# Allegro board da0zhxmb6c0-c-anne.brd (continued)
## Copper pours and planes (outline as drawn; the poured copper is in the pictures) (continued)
GND on BOTTOM (solid shape): 115.57,111.54 116.64,111.54 116.76,111.42 116.76,111.06 116.61,110.91 115.57,110.91 115.27,110.61 115.27,110.05 115.1,109.88 110.06,109.88 109.91,110.03 109.91,111.4 113.67,111.4 113.67,111.34 113.68,111.29 113.69,111.24 113.72,111.19 113.75,111.14 113.79,111.1 113.83,111.07 113.87,111.04 113.93,111.02 113.98,111.01 114.03,111.01 114.09,111.01 114.14,111.02 114.19,111.04 114.24,111.07 114.28,111.1 114.32,111.14 114.35,111.19 114.37,111.24 114.39,111.29 114.39,111.34 114.39,111.4 114.39,111.45 114.37,111.5 114.35,111.55 114.32,111.6 114.28,111.64 114.24,111.67 114.19,111.7 114.14,111.72 114.09,111.73 114.03,111.73 113.98,111.73 113.93,111.72 113.87,111.7 113.83,111.67 113.79,111.64 113.75,111.6 113.72,111.55 113.69,111.5 113.68,111.45 113.67,111.4 109.91,111.4 109.91,111.52 110.25,111.85 115.26,111.85
GND on BOTTOM (solid shape): 55.58,84.32 55.58,83.33 55.57,83.33 55.57,82.05 55.58,82.05 55.58,81.85 55.35,81.63 52.48,81.63 51.31,82.79 47.33,82.79 47.14,82.61 46.56,82.61 46.42,82.75 46.42,83.13 46.84,83.56 46.84,83.56 54.38,83.56 54.38,83.5 54.38,83.45 54.4,83.4 54.42,83.35 54.45,83.3 54.49,83.26 54.53,83.23 54.58,83.2 54.63,83.18 54.68,83.17 54.74,83.17 54.79,83.17 54.85,83.18 54.9,83.2 54.94,83.23 54.98,83.26 55.02,83.3 55.05,83.35 55.08,83.4 55.09,83.45 55.1,83.5 55.1,83.56 55.09,83.61 55.08,83.66 55.05,83.71 55.02,83.76 54.98,83.8 54.94,83.83 54.9,83.86 54.85,83.88 54.79,83.89 54.74,83.89 54.68,83.89 54.63,83.88 54.58,83.86 54.53,83.83 54.49,83.8 54.45,83.76 54.42,83.71 54.4,83.66 54.38,83.61 54.38,83.56 46.84,83.56 46.84,85.72 47.12,85.99 53.9,85.99
GND on BOTTOM (solid shape): 111.51,61.56 111.51,61.05 111.61,60.95 111.63,60.93 111.64,60.77 111.7,60.65 111.72,60.58 111.68,60.51 111.79,59.87 112.22,60.35 112.23,60.45 112.32,60.49 113.86,60.49 114.42,59.93 116.87,59.93 117.02,59.78 117.02,57.72 116.85,57.56 116.85,57.51 116.74,57.39 113.69,57.39 113.67,57.42 113.16,57.42 113.13,57.39 110.26,57.39 109.86,57.8 109.86,61.69 110.24,62.07 111,62.07
GND on BOTTOM (solid shape): outline of 89 points within 113.21,99.15 121.41,107.53
GND on BOTTOM (solid shape): 22.13,72.88 22.13,64.9 21.57,64.34 18.32,64.34 17.17,63.19 15.78,63.19 14.61,64.35 11.74,64.35 11.46,64.63 11.46,66.1 10.71,67.07 9.58,66.61 7.57,66.61 2.66,66.61 2.66,68.75 2.36,69.46 1.65,69.76 1.41,69.76 1.41,70.74 2.66,70.74 7.52,70.74 8.21,71.24 8.01,72.06 8.01,72.92 8.33,73.24 21.77,73.24
GND on BOTTOM (solid shape): outline of 86 points within 127.38,56.07 136.91,60.67
GND on BOTTOM (solid shape): 83.25,65.42 83.29,65.41 83.37,65.37 83.46,65.35 83.48,65.35 83.56,65.27 83.55,65.24 83.63,64.94 83.94,64.88 83.97,64.89 83.99,64.87 84.92,64.87 85.27,64.52 85.22,64.47 85.19,64.47 84.72,64.47 84.61,64.58 84.13,64.58 84.07,64.64 83.59,64.64 83.34,64.39 83.3,64.42 83.1,64.47 82.91,64.38 82.84,64.35 82.76,64.38 82.71,64.42 82.65,64.46 82.6,64.51 82.59,64.58 82.6,64.67 82.59,64.76 82.6,64.83 82.65,64.88 82.8,65.01 82.84,65.2 82.84,65.22 82.88,65.28 82.91,65.28 83.08,65.31 83.22,65.41
GND on BOTTOM (solid shape): 59.55,65.42 59.58,65.41 59.72,65.31 59.89,65.28 59.92,65.28 59.96,65.23 59.96,65.2 60,65.01 60.15,64.88 60.2,64.83 60.21,64.76 60.2,64.67 60.21,64.58 60.2,64.51 60.15,64.46 60.09,64.42 60.04,64.38 59.96,64.35 59.89,64.38 59.7,64.47 59.5,64.42 59.46,64.4 59.18,64.68 58.77,64.68 58.67,64.58 58.2,64.58 58.08,64.46 57.91,64.46 57.86,64.51 57.31,64.51 57.21,64.58 57.24,64.69 57.44,64.89 58.85,64.89 58.86,64.89 59.17,64.94 59.25,65.24 59.24,65.27 59.32,65.35 59.34,65.35 59.43,65.37 59.51,65.41
GND on BOTTOM (solid shape): 136.6,106.06 137.95,106.06 138.1,105.91 138.13,105.91 138.7,105.34 142.66,105.34 142.85,105.15 147.54,105.15 147.74,104.94 147.74,104.45 146.89,103.6 144.71,103.6 143.14,102.02 143.14,99.26 142.43,98.55 140.38,98.55 139.84,98.01 136.4,98.01 135.89,97.5 135.89,96.99 135.38,96.48 135.28,96.48 134.44,95.65 134.11,95.65 134.06,95.7 134.05,95.72 134.04,95.74 134.04,97 134.49,97.45 134.49,100.55 134.75,100.8 135.74,100.8 135.86,100.92 135.98,100.94 136.04,100.85 136.02,100.81 136.01,100.8 136.28,100.19 136.52,100.81 136.51,100.83 136.51,100.85 136.51,102.28 136.29,102.5 136.29,102.67 136.28,102.74 136.24,102.8 136.18,102.85 136.12,102.87 136.1,102.87 136,102.98 135.72,102.98 135.63,103.07 135.63,104.85 134.72,105.76 134.72,106.16 134.87,106.31 136.35,106.31
GND on BOTTOM (solid shape): 73.76,60.74 73.81,60.73 73.85,60.73 73.92,60.71 73.95,60.64 73.99,60.51 74.08,60.4 74.11,60.33 74.08,60.25 74.01,60.17 73.97,60.09 73.95,60.06 73.91,60.05 73.67,60.01 73.54,59.8 73.5,59.73 73.41,59.71 73.21,59.69 73.07,59.53 73.06,59.5 72.71,59.5 72.61,59.6 72.6,59.61 72.59,59.65 72.61,59.68 72.71,59.82 72.73,59.99 72.73,60.02 72.79,60.06 72.81,60.06 73,60.1 73.13,60.25 73.18,60.3 73.25,60.31 73.58,60.38 73.73,60.69 73.73,60.71
GND on BOTTOM (solid shape): 77.41,78.58 77.44,78.56 77.47,78.53 77.47,78.51 77.56,78.35 77.74,78.29 77.76,78.28 77.78,78.27 77.98,78.07 77.98,77.62 77.98,77.61 77.97,77.59 77.9,77.41 77.97,77.24 77.98,77.22 77.98,77.21 77.98,76.8 77.85,76.67 77.69,76.67 77.62,76.7 77.59,76.77 77.56,76.9 77.49,77.01 77.48,77.04 77.49,77.08 77.59,77.24 77.58,77.43 77.37,77.8 76.96,77.71 76.94,77.69 76.92,77.69 76.68,77.69 76.59,77.78 76.59,77.88 76.82,78.11 76.82,78.27 76.83,78.29 76.85,78.31 76.93,78.37 76.98,78.46 76.98,78.47 77.06,78.55 77.08,78.56 77.25,78.54 77.38,78.57
GND on BOTTOM (solid shape): 13.22,96.52 13.22,93.68 13.72,92.29 13.14,90.93 13.14,90.47 11.53,88.86 11.53,87.98 12.42,87.09 12.42,86 11.99,85.56 8.21,85.56 8.01,85.76 8.01,85.94 8.21,86.76 7.52,87.26 2.79,87.26 1.41,87.26 1.41,88.29 1.91,88.66 2.11,89.25 2.11,91.34 2.79,91.34 11.7,91.34 12.67,92.09 12.21,93.22 12.21,96.51 12.45,96.76 12.99,96.76
GND on BOTTOM (solid shape): 82,60.89 82.07,60.88 82.11,60.81 82.34,60.54 82.69,60.6 82.7,60.61 82.94,60.63 82.95,60.63 83.17,60.64 83.32,60.79 83.36,60.82 83.4,60.81 83.41,60.8 83.43,60.76 83.41,60.72 83.3,60.52 83.34,60.29 83.34,60.19 83.25,60.14 83.22,60.14 83.21,60.14 83.04,60.19 82.88,60.14 82.87,60.14 82.66,60.14 82.65,60.14 82.5,60.18 82.35,60.14 82.34,60.14 82.25,60.14 82.14,60.04 82.14,59.78 82.07,59.71 81.92,59.71 81.82,59.8 81.82,60.22 81.82,60.24 81.8,60.35 81.75,60.45 81.73,60.53 81.77,60.6 81.87,60.71 81.92,60.85 81.93,60.88 81.97,60.89
GND on BOTTOM (solid shape): 87.15,82.18 87.15,82.13 87.21,81.99 87.35,81.93 87.65,81.93 87.71,81.94 87.77,81.96 87.78,81.97 87.82,81.97 87.89,81.91 87.89,81.09 87.86,81.06 87.86,80.61 87.38,80.14 87.31,80.13 87.23,80.12 87.08,80.06 87.02,79.92 87.02,79.8 87.02,79.73 87.01,79.71 86.69,79.39 85.29,79.39 85.15,79.54 85.05,79.54 85.01,79.57 84.15,79.57 83.97,79.75 83.97,80.18 84.18,80.38 84.21,80.39 84.39,80.45 84.49,80.61 84.49,80.62 84.69,80.82 84.89,80.82 84.91,80.81 85.13,80.6 85.13,80.58 85.45,80.22 85.83,80.5 85.84,80.52 85.85,80.53 85.85,80.89 85.42,81.32 85.4,81.33 85.18,81.4 84.96,81.32 84.5,81.32 84.37,81.19 84.09,81.19 83.52,81.76 83.52,81.99 83.7,82.17 83.7,82.46 83.61,82.56 83.61,82.8 84.01,83.2 86.13,83.2
GND on BOTTOM (solid shape): outline of 119 points within 94.31,97.53 103.56,107.2
GND on BOTTOM (solid shape): outline of 146 points within 133.12,78.73 145.75,90.85
GND on BOTTOM (solid shape): 6.73,8.85 7.01,7.29 6.46,5.8 5.75,5.09 5.26,4.8 4.71,4.61 4.32,4.52 4.32,1.52 6.32,1.52 6.39,1.95 6.44,2.25 6.5,2.55 6.6,2.72 6.59,2.93 6.81,3.64 7.08,4.33 7.39,4.54 7.36,4.91 7.77,5.62 8.25,6.3 9.34,6.3 9.44,6.24 9.42,6.13 8.02,3.95 7.35,1.45 7.33,1.45 7.3,0.97 7.15,0.64 6.81,0.51 3.8,0.51 3.45,0.65 3.31,1 3.31,5.54 4,5.54 5.78,6.62 5.65,8.7 5.71,8.77 5.76,8.85
GND on BOTTOM (solid shape): outline of 169 points within 58.9,88.27 67.76,91.86
GND on BOTTOM (solid shape): 77.43,64.62 77.52,64.63 77.58,64.57 77.72,64.36 77.96,64.29 77.98,64.29 78.01,64.25 78.01,64.23 78.2,63.89 78.57,64.03 78.66,64.08 78.75,64.03 78.84,63.92 78.97,63.87 79,63.87 79.02,63.83 79.01,63.8 79.05,63.47 79.33,63.3 79.4,63.26 79.42,63.19 79.48,63.01 79.64,62.89 79.7,62.84 79.71,62.77 79.71,62.73 79.7,62.68 79.69,62.65 79.66,62.63 79.53,62.58 79.44,62.47 79.41,62.45 79.37,62.45 79.22,62.49 79.06,62.45 79.02,62.48 79.02,62.5 78.97,62.63 78.87,62.72 78.82,62.81 78.87,62.9 78.91,63.4 78.43,63.25 78.38,63.2 78.31,63.19 78.19,63.19 78.07,63.17 78.03,63.19 78.03,63.22 77.92,63.41 77.72,63.48 77.64,63.5 77.61,63.57 77.57,63.71 77.47,63.82 77.44,63.9 77.47,63.97 77.59,64.27 77.43,64.54 77.4,64.58 77.43,64.62
GND on BOTTOM (solid shape): outline of 82 points within 76.47,59.37 78.62,63.18
GND on BOTTOM (solid shape): outline of 571 points within 2.11,97.59 152.08,115.49
GND on BOTTOM (solid shape): outline of 528 points within 111.01,32.96 131.71,40.73
GND on BOTTOM (solid shape): outline of 1092 points within 16.41,9.41 158.36,91.52
GND on BOTTOM (solid shape): outline of 11624 points within 57.57,57.72 85.2,83.91
GND on VCC (solid shape): outline of 314 points within 123.34,32.88 129.51,41.98
GND on VCC (solid shape): outline of 607 points within 66.93,93.56 79,99.91
GND on VCC (solid shape): outline of 1890 points within 98.43,71.97 117.98,92.29
GND on VCC (solid shape): outline of 1797 points within 2.87,2.03 26.42,36.41
GND on VCC (solid shape): outline of 2600 points within 3.6,50.76 33.4,95.11
GND on VCC (solid shape): outline of 4444 points within 114.68,20.43 159.61,112.47
GND on VCC (solid shape): outline of 28074 points within 33.91,32.86 112.4,73.24
GND on IN1 (solid shape): 10.8,19.85 10.8,17.14 10.57,16.91 6.63,16.91 6.35,17.19 6.35,19.8 6.53,19.98 10.67,19.98
GND on IN1 (solid shape): 27.43,26.99 27.43,24.98 27.31,24.86 25.32,24.86 25.12,25.06 25.12,26.99 25.32,27.19 27.23,27.19
GND on IN1 (solid shape): 41.99,66.14 41.99,64.3 41.89,64.2 39.57,64.2 39.45,64.33 39.45,66.41 39.65,66.61 41.51,66.61
GND on IN1 (solid shape): 99.92,23.84 99.92,22.24 99.67,21.99 98.25,21.99 98.05,22.19 98.05,23.97 98.1,24.02 99.75,24.02
GND on IN1 (solid shape): 30.08,64.83 30.08,62.18 29.79,61.89 27.1,61.89 26.9,62.09 26.9,64.23 27.16,64.49 27.16,65.2 27.26,65.29 29.61,65.29
GND on IN1 (solid shape): 33.05,58.12 33.05,57.56 32.47,56.97 32.46,56.96 32.46,55.06 32.13,54.73 29.49,54.73 28.91,55.31 28.91,58.18 29.11,58.38 32.79,58.38
GND on IN1 (solid shape): 12.47,52.4 12.29,51.56 11.78,50.88 3.67,50.88 3.67,49.64 3.34,49.31 3.34,49.29 2.92,49.29 2.66,49.56 2.66,51.89 8.38,51.89 9.58,51.89 9.78,51.65 10.05,51.48 10.45,51.39 10.85,51.48 11.29,51.85 11.46,52.4 11.46,53.38 11.64,53.56 12.47,53.56
GND on IN1 (solid shape): 6.73,8.85 6.73,6.25 4.71,4.61 4.32,4.52 4.32,1.52 6.32,1.52 6.39,1.95 6.43,2.23 6.49,2.5 6.63,2.72 6.61,2.98 6.81,3.65 7.07,4.3 7.42,4.53 7.37,4.94 8.67,6.82 10.38,8.33 10.94,8.33 11.13,8.14 11.13,7.61 8.55,4.95 7.35,1.45 7.33,1.45 7.3,0.97 7.15,0.64 6.81,0.51 3.8,0.51 3.45,0.65 3.31,1 3.31,5.54 4,5.54 5.66,6.41 5.87,8.27 5.77,8.49 5.65,8.7 5.71,8.77 5.76,8.85
GND on IN1 (solid shape): outline of 575 points within 2.11,96.75 152.02,115.49
GND on IN1 (solid shape): outline of 931 points within 28.27,14.11 157.74,91.52
GND on IN1 (solid shape): outline of 1253 points within 1.41,64.33 20.37,100.11
GND on IN2 (solid shape): 27.43,27.02 27.43,24.96 27.33,24.86 25.27,24.86 25.17,24.96 25.17,27.02 25.3,27.14 27.31,27.14
GND on IN2 (solid shape): 41.99,66.03 41.99,64.25 41.94,64.2 39.63,64.2 39.37,64.46 39.37,66.44 39.6,66.66 41.36,66.66
GND on IN2 (solid shape): 100.05,23.74 100.05,22.25 99.77,21.96 98.2,21.96 98.02,22.14 98.02,23.82 98.2,23.99 99.8,23.99
GND on IN2 (solid shape): 10.8,19.95 10.8,15.93 10.58,15.71 8.16,15.71 8.06,15.61 6.53,15.61 6.4,15.74 6.4,19.83 6.58,20.01 10.75,20.01
GND on IN2 (solid shape): 29.93,58.28 32.62,58.28 32.88,58.01 33.19,58.01 33.3,57.9 33.3,57.42 32.64,56.76 32.64,55.26 32.13,54.75 29.34,54.75 29.28,54.81 29.28,54.99 28.78,55.49 28.78,58.05 29.11,58.38 29.82,58.38
GND on IN2 (solid shape): 30.35,65.01 30.35,62.34 30.34,62.31 30.3,62.29 26.93,62.29 26.89,62.31 26.87,62.34 26.87,64.96 27.2,65.29 30.07,65.29
GND on IN2 (solid shape): 12.47,52.4 12.29,51.56 11.77,50.87 9.12,50.87 9.11,50.88 3.67,50.88 3.67,49.66 3.29,49.28 2.88,49.28 2.66,49.5 2.66,51.89 8.48,51.89 9.58,51.89 10.71,51.43 11.46,52.4 11.46,53.48 11.53,53.56 12.47,53.56
GND on IN2 (solid shape): 12.38,72.1 13.81,72.1 14.64,72.93 18.19,72.93 20.71,70.4 20.71,67.47 17.57,64.33 11.81,64.33 11.46,64.68 11.46,66.1 10.71,67.07 9.58,66.61 8.79,66.61 2.66,66.61 2.66,68.75 2.36,69.46 1.65,69.76 1.41,69.76 1.41,70.74 2.66,70.74 7.52,70.74 8.21,71.24 8.01,72.06 8.01,72.92 8.33,73.25 11.23,73.25
GND on IN2 (solid shape): 12.74,100.09 13.7,98.67 13.22,97.02 13.22,93.68 13.68,91.91 12.52,90.5 11.92,89.9 11.92,86.02 11.47,85.56 8.21,85.56 8.01,85.77 8.01,85.94 8.21,86.76 7.52,87.26 2.79,87.26 1.41,87.26 1.41,88.29 1.91,88.66 2.11,89.25 2.11,91.34 2.79,91.34 11.7,91.34 12.67,92.09 12.21,93.22 12.21,97.48 12.71,98.37 12.18,99.24 12.18,99.85 12.41,100.09
GND on IN2 (solid shape): 6.73,8.85 6.73,6.25 4.71,4.61 4.32,4.52 4.32,1.52 6.32,1.52 6.39,1.95 6.43,2.23 6.49,2.5 6.63,2.72 6.61,2.98 6.81,3.65 7.07,4.3 7.42,4.53 7.37,4.94 8.67,6.82 10.38,8.33 10.94,8.33 11.13,8.14 11.13,7.61 8.55,4.95 7.35,1.45 7.33,1.45 7.3,0.97 7.15,0.64 6.81,0.51 3.8,0.51 3.45,0.65 3.31,1 3.31,5.54 4,5.54 5.63,6.38 5.9,8.19 5.79,8.45 5.65,8.7 5.71,8.77 5.76,8.85
GND on IN2 (solid shape): outline of 514 points within 2.11,97.13 152.67,115.49
GND on IN2 (solid shape): outline of 620 points within 149.48,48.95 159.25,102.75
GND on IN2 (solid shape): outline of 628 points within 16.41,9.41 157.09,42.35
GND on GND (solid shape): outline of 90983 points within 1.41,0.51 162.79,115.49
24707_LX on TOP (solid shape): 91.92,23.54 91.92,22.8 92.06,22.66 92.15,22.66 92.15,22.65 93.18,22.65 93.18,22.66 94.03,22.66 94.34,22.34 94.34,22.19 94.58,21.96 95.87,21.96 95.93,21.96 96.62,22.65 96.88,22.65 96.93,22.6 97.62,22.6 97.7,22.52 97.7,22.43 97.65,22.38 96.99,22.38 96.95,22.34 96.92,22.34 96.92,22.31 96.83,22.22 96.82,22.22 96.82,22.2 96.79,22.18 96.79,21.76 96.33,21.3 92.09,21.3 91.57,21.82 91.57,21.82 90.27,23.12 90.27,23.95 90.43,24.11 91.35,24.11
24707_LX on BOTTOM (solid shape): 93.42,26.72 93.42,22.7 93.37,22.64 93.36,22.64 93.27,22.55 93.27,21.89 93.25,21.87 90.86,21.87 90.47,21.48 88.29,21.48 88.19,21.58 88.19,25.16 88.34,25.31 89.45,25.31 91.05,26.92 93.22,26.92
24737_BST on TOP (solid shape): 96.9,23.61 97.69,23.61 97.71,23.59 97.71,23.38 97.69,23.36 96.93,23.36 96.88,23.31 96.47,23.31 96.28,23.11 96.03,23.11 95.71,22.8 95.02,22.8 94.95,22.88 94.95,23.59 95,23.64 96.88,23.64
24737_DH on TOP (solid shape): 97.76,23.1 97.76,22.85 97.75,22.84 96.92,22.84 96.66,22.84 95.88,22.06 94.63,22.06 94.45,22.24 94.45,22.53 94.61,22.69 94.71,22.69 94.73,22.67 95.75,22.67 96.08,23 96.32,23 96.43,23.11 97.74,23.11
24737_DH on BOTTOM (solid shape): 94.96,22.63 94.96,22.56 95.05,22.47 95.08,22.44 95.08,22.35 94.66,21.93 93.97,21.93 93.91,21.87 93.48,21.87 93.48,22.57 93.62,22.72 94.87,22.72
24737_DL on TOP (solid shape): 97.94,25.04 98.04,25.04 98.11,25.01 98.15,24.94 98.15,24.32 98,24.32 97.94,24.26 96.96,24.26 96.92,24.22 96.82,24.22 96.82,24.22 95.08,24.22 94.77,24.53 94.77,24.83 94.92,24.98 95.35,24.98 95.65,24.68 95.66,24.68 95.79,24.55 96.34,24.55 96.85,25.06 97.83,25.06
24737_DL on BOTTOM (solid shape): 95.4,24.74 95.4,24.5 94.95,24.04 93.9,24.04 93.8,24.15 93.8,24.5 93.83,24.52 94.59,24.52 94.69,24.62 94.69,24.7 94.89,24.91 95.23,24.91
24737_REGN on TOP (solid shape): 93.41,27.51 93.41,25.78 93.69,25.5 94.2,25.5 94.57,25.13 94.57,24.43 94.88,24.12 97.71,24.12 97.75,24.08 97.75,23.86 97.74,23.85 96.92,23.85 96.84,23.76 94.73,23.76 94.59,23.9 93.97,23.9 92.44,25.44 92.44,27.58 92.69,27.83 93.09,27.83
51216DRVH on BOTTOM (solid shape): 21.16,44.34 21.16,43.68 21.74,43.09 21.74,42.21 21.62,42.08 21.06,42.08 20.63,42.51 20.63,44.26 20.75,44.39 21.11,44.39
51216DRVH on IN1 (solid shape): 22.02,43.78 22.02,42.15 21.95,42.08 21.26,42.08 21.23,42.11 21.23,43.8 21.34,43.91 21.9,43.91
51216DRVL on BOTTOM (solid shape): 28.58,47.18 28.58,46.93 28.33,46.69 27.73,46.69 27.56,46.52 27.13,46.52 27.08,46.57 27.08,47.31 27.13,47.36 27.56,47.36 27.64,47.29 27.89,47.29 27.99,47.39 28.37,47.39
51216SW on TOP (solid shape): 28.36,45.37 28.36,44.33 28.25,44.21 26.57,44.21 26.48,44.3 26.48,45.32 26.8,45.63 28.09,45.63
51216SW on BOTTOM (solid shape): 28.61,45.8 28.61,43.49 28.6,43.48 28.6,41.65 26.81,39.85 22.45,39.85 22.02,40.28 22.02,43.04 21.36,43.7 21.36,44.36 21.62,44.62 23.42,44.62 24.03,45.23 24.03,45.96 24.33,46.27 28.14,46.27
+CLKDDR_1P35_PWR on IN1 (solid shape): outline of 487 points within 71.51,50.87 73.27,66.83
+LCDVCC on BOTTOM (solid shape): 64.36,96.56 64.36,95.09 64.49,94.96 66.12,94.96 66.19,94.88 66.19,94.2 66.42,93.97 66.75,93.97 66.9,93.82 66.9,93.79 67.54,93.16 67.54,92.8 67.26,92.52 65.76,92.52 65.57,92.71 65.57,94.05 65.2,94.05 65.12,94.13 65.07,94.13 65.03,94.17 63.88,94.17 63.58,94.48 63.55,94.48 63.55,94.48 63.29,94.48 63.16,94.62 63.16,95.1 64.12,95.1 64.12,96.4 63.88,96.4 63.88,95.1 63.62,95.1 63.62,96.4 63.38,96.4 63.38,95.1 63.16,95.1 63.16,96.45 63.35,96.64 64.29,96.64
+PLLDDR_1P35_PWR on IN1 (solid shape): outline of 752 points within 68.24,49.47 71.44,66.79
+TPVDD_1 on TOP (solid shape): 47.08,26.12 47.08,25.42 47.43,25.06 48.09,25.06 48.1,25.05 48.57,25.05 48.9,24.73 48.9,21.53 47.7,20.34 45.37,20.34 45.29,20.41 45.29,20.67 44.83,21.12 44.83,22.19 45.34,22.7 45.98,22.7 46.36,23.08 46.36,24.48 46.23,24.6 46.23,26.25 46.35,26.38 46.82,26.38
+TPVDD_1 on BOTTOM (solid shape): 47.45,24.48 51.69,24.48 52.22,23.94 52.22,22.09 51.39,21.25 49.89,21.25 49.84,21.3 49.84,22.82 49.68,22.98 46.48,22.98 46.23,23.23 46.23,24.73 46.51,25.01 46.91,25.01
+TPVDD_1 on IN2 (solid shape): 47.3,25.01 47.3,23.48 46.86,23.04 46.42,23.04 46,23.46 46,25.26 46.1,25.36 46.94,25.36
+VGG on TOP (solid shape): outline of 763 points within 73,61.37 119.46,74.51
+VGG on BOTTOM (solid shape): 120.52,65.62 120.52,62.99 120.51,62.95 120.47,62.94 119.58,62.94 119.55,62.96 117.86,62.96 117.86,62.44 119.55,62.44 119.58,62.47 120.35,62.47 120.52,62.29 120.52,61.41 119.23,60.12 118.45,60.12 118.36,60.04 114.46,60.04 113.9,60.6 113.76,60.6 113.72,60.6 113.67,60.6 112.42,60.6 112.34,60.64 112.33,60.74 112.2,61.17 111.74,61.14 111.71,61.13 111.67,61.14 111.63,61.18 111.63,61.81 111.25,62.19 110.24,62.19 110.03,62.4 110.03,63.7 110.04,63.72 110.05,63.73 110.21,63.9 110.21,66.69 110.41,66.89 119.25,66.89
+VGG on BOTTOM (solid shape): outline of 96 points within 72.73,67.57 77.46,71.08
+VGG on VCC (solid shape): outline of 4973 points within 72.42,59.65 119.76,80.36
ADOGND on TOP (solid shape): 10.04,26.15 10.04,25.51 10.06,25.49 10.06,25.3 10.04,25.28 10.04,24.69 9.96,24.6 8.99,24.6 8.81,24.78 8.81,26.13 8.89,26.2 9.98,26.2
ADOGND on TOP (solid shape): 2.29,34.26 2.29,32.73 3.91,31.1 3.91,27.78 4.44,27.25 4.44,25.77 3.66,24.98 3.66,23.74 3.25,23.33 3.25,18.22 3.24,18.2 3.23,18.18 3.1,17.92 3.21,17.65 3.22,17.63 3.23,17.61 3.23,17.01 2.69,16.47 2.69,13.86 2.97,13.58 3.2,13.58 3.33,13.45 3.33,11.88 3.4,11.8 4.98,11.8 5.41,12.23 5.41,12.37 5.51,12.47 5.91,12.47 5.97,12.41 5.97,11.01 5.93,10.98 5.69,10.98 5.47,11.19 2.87,11.19 2.39,10.71 2.39,10.04 2.38,9.85 2.38,9.67 2.36,9.59 2.28,9.56 0.56,9.56 0.52,9.57 0.51,9.61 0.51,34.59 0.52,34.63 0.56,34.64 1.91,34.64
ADOGND on TOP (solid shape): 13.39,48.44 13.8,48.11 14.12,47.69 14.35,46.99 14.32,46.24 14.15,45.78 13.87,45.37 13.87,41.48 14.37,40.23 13.97,38.94 13.95,38.92 13.93,38.91 13.3,38.91 13.03,39.18 13.03,39.38 13.04,39.41 13.05,39.42 13.35,40.25 12.88,41.01 12.86,41.02 12.86,41.05 12.86,45.8 12.86,45.83 12.88,45.84 13.36,46.68 12.92,47.53 12.9,47.55 12.9,47.57 12.9,48.2 13.14,48.44 13.35,48.44
ADOGND on BOTTOM (solid shape): 1.52,34.49 1.52,10.57 2.07,10.57 2.29,10.35 2.29,9.66 2.19,9.56 0.51,9.56 0.51,34.64 1.37,34.64
ADOGND on BOTTOM (solid shape): 13.39,48.44 13.8,48.11 14.12,47.69 14.35,46.99 14.32,46.24 14.15,45.78 13.87,45.37 13.87,41.48 14.36,40.34 14.09,39.12 14.07,39.1 14.05,39.09 13.12,39.09 13.03,39.18 13.03,39.38 13.04,39.41 13.05,39.42 13.35,40.25 12.88,41.01 12.86,41.02 12.86,41.05 12.86,45.8 12.86,45.83 12.88,45.84 13.36,46.68 12.92,47.53 12.9,47.55 12.9,47.57 12.9,48.2 13.14,48.44 13.35,48.44
ADOGND on VCC (solid shape): outline of 1376 points within 2.03,9.36 18.29,50.18
ADOGND on IN1 (solid shape): 1.52,34.39 1.52,10.57 2.04,10.57 2.29,10.33 2.29,9.69 2.16,9.56 0.51,9.56 0.51,34.64 1.27,34.64
ADOGND on IN1 (solid shape): 13.39,48.44 14.35,47.02 13.87,45.37 13.87,41.48 14.37,40.21 13.95,38.91 13.3,38.91 13.03,39.18 13.03,39.41 13.35,40.26 12.86,41.02 12.86,45.83 13.36,46.68 12.9,47.55 12.9,48.2 13.14,48.44 13.35,48.44
ADOGND on IN2 (solid shape): 1.52,34.44 1.52,10.57 2.04,10.57 2.29,10.33 2.29,9.69 2.16,9.56 0.51,9.56 0.51,34.64 1.32,34.64
ADOGND on IN2 (solid shape): 14.37,48.2 14.37,45.65 13.87,45.15 13.87,41.48 14.37,40.19 13.92,38.88 13.18,38.88 12.96,39.1 12.96,39.35 13.36,40.21 12.86,41.02 12.86,45.83 13.35,46.57 13.06,47.41 13.06,48.38 13.29,48.61 13.97,48.61
ADOGND on GND (solid shape): outline of 1723 points within 0.51,9.36 18.29,50.18
BAT-V on TOP (solid shape): 82.93,26.19 82.93,18.25 82.83,18.15 77.7,18.15 77.42,18.43 77.42,21.86 77.24,22.04 77.23,22.08 77.24,22.1 77.31,22.24 77.32,22.41 77.06,22.85 76.57,22.7 76.48,22.65 76.4,22.69 76.09,22.87 75.75,22.73 75.68,22.7 75.6,22.73 75.12,22.83 74.89,22.39 74.89,22.28 74.92,22.16 74.91,22.07 74.83,22.02 67.91,22.02 66.17,20.28 62.61,20.28 61.72,21.17 61.72,26.51 62.69,27.47 81.65,27.47
BAT-V on BOTTOM (solid shape): 80.29,29.23 80.29,25.97 80.21,25.9 78.92,25.9 77.88,26.94 75.77,26.94 75.34,27.37 75.34,28.46 75.79,28.92 78.77,28.92 79.17,29.33 80.19,29.33
BAT-V on BOTTOM (solid shape): 66.68,28.72 66.68,23.31 66.66,23.29 66.66,21.11 65.91,20.36 62.26,20.36 61.06,21.55 61.06,23.76 59.46,25.36 59.46,28.62 59.77,28.92 62.54,28.92 62.79,28.67 65.43,28.67 65.81,29.05 66.35,29.05
BAT-V on IN2 (solid shape): outline of 589 points within 60.55,18.54 80.39,27.43
BMPD_1P05_PWR on TOP (solid shape): outline of 461 points within 70.11,74.05 75.01,85.09
BMPD_1P05_PWR on IN2 (solid shape): 73.02,77.27 73.04,77.27 73.06,77.25 73.13,77.19 73.22,77.15 73.23,77.14 73.66,76.71 73.66,76.55 73.62,76.47 73.52,76.46 73.04,76.12 73.52,75.79 73.61,75.78 73.66,75.69 73.66,75.18 73.58,75.1 73.55,75.1 72.99,74.55 72.9,74.52 72.83,74.57 72.35,74.74 72.19,74.26 72.18,74.16 72.1,74.11 71.6,74.11 71.5,74.22 71.5,75.96 71.56,76.05 71.67,76.03 72.01,75.69 72.65,75.69 72.65,76.33 72.08,76.89 72.07,76.93 72.08,76.96 72.39,77.27
CCD_PWR on TOP (solid shape): 66.32,101.64 66.32,97.07 66.23,96.97 65.4,96.97 65.15,97.22 65.15,99.27 65.23,99.35 65.33,99.65 65.17,99.91 65.16,99.93 65.15,99.95 65.15,101.59 65.33,101.77 66.19,101.77
CCD_PWR on BOTTOM (solid shape): 66.19,97.63 66.19,97.07 66.08,96.95 65.55,96.95 65.36,96.76 65.36,95.09 65.34,95.07 65.17,95.07 65.14,95.08 65.12,95.12 65.12,97.53 65.38,97.78 66.04,97.78
CF3_3P3_PWR on TOP (solid shape): 86.29,84.32 86.4,84.3 86.46,84.24 86.46,81.99 86.67,81.79 87.22,81.79 87.64,81.37 87.64,81.02 87.47,80.85 86.02,80.85 85.52,80.35 85.4,80.35 85.24,80.51 85.24,82.21 85.44,82.41 85.44,84.27 85.52,84.34 86.21,84.34
CORE_1P05_PWR on TOP (solid shape): outline of 751 points within 61.09,71.79 69.79,88.15
CORE_1P05_PWR on BOTTOM (solid shape): 64.91,88.15 65.1,88.1 65.3,88.15 66.22,88.15 66.35,88.02 66.35,87.1 66.33,87.08 66.31,87.07 66.08,86.91 65.96,86.66 65.94,86.63 65.91,86.62 65.79,86.62 65.69,86.52 65.66,86.5 65.63,86.51 65.5,86.56 65.36,86.58 65.29,86.58 65.26,86.59 65.24,86.6 64.73,86.88 64.25,86.55 64.17,86.49 64.08,86.52 63.09,87.5 63.09,87.93 63.32,88.15
CORE_1P05_PWR on BOTTOM (solid shape): 68.18,74.63 68.23,74.58 68.87,73.94 68.88,73.93 68.92,73.86 68.99,73.8 69.01,73.78 69.01,73.76 69.01,73.65 69.32,73.35 69.34,73.35 69.35,73.34 69.6,73.3 69.82,73.45 69.83,73.47 69.86,73.47 69.95,73.47 70.05,73.37 70.05,73.02 69.47,72.43 69.45,72.42 69.2,72.23 69.21,71.9 69.22,71.89 69.22,71.87 69.32,71.77 69.32,71.59 69.22,71.49 68.96,71.49 68.2,72.25 66.78,72.25 66.65,72.38 66.65,72.53 67.69,73.57 67.69,73.73 67.87,73.9 67.88,74.03 67.87,74.16 67.72,74.31 67.72,74.54 67.9,74.72 68.1,74.72
CORE_V1P15_PWR on TOP (solid shape): 96.82,66.92 101.83,66.92 101.86,66.89 101.86,66.23 101.71,66.09 100.84,66.09 100.81,66.06 100.54,66.06 100.51,66.09 99.48,66.09 99.45,66.06 97.76,66.06 97.75,66.06 97.61,66.09 97.47,66.06 97.46,66.06 96.83,66.06 96.4,66.48 96.4,66.49 96.34,66.6 96.24,66.65 96.23,66.65 95.64,67.24 95.64,67.77 95.78,67.91 95.83,67.91
CORE_V1P15_PWR on TOP (solid shape): outline of 138 points within 61.24,66 70.54,69.08
CORE_V1P15_PWR on IN1 (solid shape): outline of 268 points within 69.26,67.26 96.66,71.39
DDI_1P15_PWR on TOP (solid shape): 75.06,68.44 75.06,67.17 74.93,67.05 74.55,67.05 74.42,67.17 74.42,67.53 74.04,67.91 73.69,67.91 73.46,68.14 73.46,68.44 73.56,68.54 74.96,68.54
DDI_1P15_PWR on IN1 (solid shape): outline of 677 points within 67.69,66.58 84.25,69.43
DDR_1P05_PWR on TOP (solid shape): outline of 499 points within 73.1,64.23 86.36,66.89
DDR_1P05_PWR on BOTTOM (solid shape): 74.63,67.05 74.63,66.87 73.74,65.98 73.53,65.98 73.05,66.46 73.05,66.72 73.51,67.17 74.5,67.17
DDR_1P05_PWR on IN2 (solid shape): 73.61,66.69 73.61,66.11 73.22,65.71 70.3,65.71 70.05,65.95 69.66,65.95 69.46,66.02 69.26,65.95 68.67,65.95 68.57,66 68.46,66.02 68.44,66.02 68.28,66.18 68.28,66.4 68.32,66.49 68.34,66.58 68.34,66.6 68.39,66.65 68.59,66.85 69.01,66.85 69.24,66.61 70.44,66.61 70.74,66.31 70.79,66.31 70.79,66.3 71.06,66.22 71.3,66.36 71.31,66.38 71.39,66.41 71.47,66.37 71.78,66.23 72.06,66.41 72.15,66.46 72.24,66.41 72.65,66.25 72.9,66.62 72.9,66.77 73,66.87 73.43,66.87
EC_114 on BOTTOM (solid shape): 135.33,39.62 135.33,37.51 135.1,37.28 135.1,37.28 135.03,37.2 134.28,37.2 133.73,37.75 133.73,37.76 133.45,38.04 133.45,38.57 133.79,38.9 133.79,39.41 134.09,39.72 135.24,39.72
FUSE1_1P05_PWR on TOP (solid shape): outline of 348 points within 79,78.39 81.56,86.96
FUSE_1P05_PWR on TOP (solid shape): outline of 101 points within 74.63,75.02 76.43,86.82
FUSE_1P8_PWR on TOP (solid shape): outline of 140 points within 77.1,75.18 89.44,79.78
GPIOCF1_1P8_PWR on TOP (solid shape): outline of 106 points within 75.26,63.95 88.26,68.56
GPIOCF1_1P8_PWR on IN2 (solid shape): outline of 271 points within 68.42,67.1 77.06,70.88
GPIOCF2_1P8_PWR on TOP (solid shape): outline of 240 points within 76.05,73.19 89.45,78.32
HDMI_5V on TOP (solid shape): outline of 94 points within 9.64,82.41 16.77,86.27
ICLK_1P05_PWR on TOP (solid shape): outline of 185 points within 75.26,73.29 79.76,86.96
ICLK_VSFR_1P24_PWR on IN1 (solid shape): outline of 369 points within 68.66,73.24 71.49,78.7
L_SPK+ on TOP (solid shape): 32.56,27.7 32.56,26.43 32.49,26.36 31.78,26.36 31.07,27.07 31.07,27.73 31.24,27.9 32.36,27.9
L_SPK+ on TOP (solid shape): 8.49,15.18 8.49,13.43 8.34,13.29 8.34,12.41 8.2,12.26 7.97,12.26 7.83,12.4 7.83,13.38 8.29,13.83 8.29,15.18 8.29,15.19 8.48,15.19
L_SPK+ on IN2 (solid shape): 32.39,27.75 32.39,27.35 32.06,27.02 31.22,27.02 30.68,26.48 30.07,27.09 30.94,27.96 32.18,27.96
L_SPK+ on IN2 (solid shape): 12.36,15.85 11.21,14.71 8.99,14.71 8.3,14.02 8.3,11.67 8.25,11.62 7.96,11.62 7.84,11.73 7.84,13.35 7.84,13.35 7.84,13.79 7.93,13.88 7.93,15.12 8.27,15.45 10.72,15.45 11.41,16.14 12.07,16.14
L_SPK+_1 on TOP (solid shape): 35.22,27.45 35.22,26.37 35.21,26.36 33.02,26.36 32.84,26.53 32.84,27.55 33.17,27.88 34.79,27.88
L_SPK+_1 on BOTTOM (solid shape): 35.1,27.75 35.1,27.3 34.8,26.99 33.71,26.99 33.61,26.89 33.6,26.89 32.58,25.86 32.58,25.86 32.37,25.65 32.37,23.27 31.58,23.27 31.58,26.11 33.38,27.9 34.95,27.9
L_SPK- on TOP (solid shape): 31.62,26 32.08,26 32.56,25.52 32.56,24.55 32.46,24.45 31.34,24.45 30.71,25.09 30.71,26.23 30.84,26.36 31.27,26.36
L_SPK- on TOP (solid shape): 8.88,15.18 8.88,14.05 8.97,13.97 8.97,12.37 8.87,12.27 8.61,12.27 8.5,12.38 8.5,13.29 8.6,13.39 8.6,13.96 8.69,14.05 8.69,15.18 8.69,15.19 8.88,15.19
L_SPK- on IN2 (solid shape): 31.88,26.1 31.88,24.22 31.31,23.65 30.91,24.04 30.91,26.23 31.12,26.43 31.55,26.43
L_SPK- on IN2 (solid shape): 13.26,15.13 13.26,14.93 11.97,13.64 9.17,13.64 8.94,13.41 8.93,13.29 8.93,11.63 8.86,11.56 8.67,11.56 8.56,11.68 8.56,13.89 9.09,14.42 10.51,14.42 10.51,14.41 11.48,14.41 12.37,15.31 13.08,15.31
L_SPK-_1 on TOP (solid shape): 35.15,25.75 35.15,24.58 35.03,24.45 33.05,24.45 32.84,24.65 32.84,25.9 33.05,26.1 34.8,26.1
L_SPK-_1 on BOTTOM (solid shape): 34.85,26.43 34.85,25.7 34.7,25.54 33.72,25.54 33.62,25.44 33.62,23.27 32.83,23.27 32.83,25.76 33.71,26.63 34.65,26.63
LED_PWR on BOTTOM (solid shape): 64.87,97.63 64.87,95.16 64.86,95.13 64.82,95.11 64.67,95.11 64.62,95.16 64.62,96.4 64.62,96.4 64.62,96.69 64.06,97.25 64.06,97.78 64.21,97.93 64.57,97.93
LGATE_VCORE on BOTTOM (solid shape): 39.35,78.43 39.35,76.81 39.27,76.73 38.52,76.73 38.41,76.85 38.41,78.83 38.52,78.95 38.82,78.95
LGATE_VCORE on BOTTOM (solid shape): 40.36,69.43 40.47,69.36 40.6,69.33 40.62,69.33 40.77,69.18 40.77,68.47 40.59,68.29 40.59,67.22 40.58,67.19 40.54,67.17 40.44,67.17 40.41,67.19 40.39,67.22 40.39,68.12 40.39,68.12 40.39,68.16 40.3,68.25 40.3,68.27 39.91,68.66 39.91,69.27 40.07,69.43
LGATE_VGG on BOTTOM (solid shape): 126.82,60.34 126.82,59.35 126.32,58.84 126.04,58.84 125.1,59.78 125.1,60.16 125.35,60.42 126.74,60.42
LX_1P8 on BOTTOM (solid shape): 110.67,107.2 110.67,104.54 110.76,104.44 110.76,104.39 111.92,103.23 111.97,103.23 112.17,103.04 112.17,102.89 112.15,102.86 112.12,102.84 111.17,102.84 111.17,102.64 112.12,102.64 112.15,102.63 112.17,102.59 112.17,102.45 112.16,102.44 111.17,102.44 111.17,102.43 110.76,102.43 110.5,102.7 108.98,102.7 107.37,104.31 107.37,107.08 107.89,107.6 110.27,107.6
NB670SW on BOTTOM (solid shape): 134.9,95.32 134.9,92.32 135.21,92.01 135.21,89.32 134.93,89.04 134.93,88.86 133.61,87.54 131.34,87.54 130.28,88.61 130.28,93.36 130.38,93.46 130.79,93.46 131.24,93.01 133.17,93.01 133.43,93.26 133.43,95.29 133.63,95.49 134.72,95.49
NB671BST_S on BOTTOM (solid shape): 132.26,110.71 132.26,109.87 132.16,109.77 131.53,109.77 131.37,109.61 131.34,109.61 131.34,109.58 131.1,109.34 130.5,109.34 130.34,109.5 130.34,110.31 130.91,110.89 132.08,110.89
NB671SW on BOTTOM (solid shape): 130.28,109.21 130.76,109.21 130.84,109.13 130.84,108.6 132.08,107.36 132.69,107.36 133.05,107 134.32,107 134.51,106.81 134.51,105.59 134.37,105.45 133.22,105.45 133.22,105.45 133.15,105.45 132.54,104.83 132.54,103.95 131.88,103.29 129.03,103.29 128.8,103.52 128.8,103.98 128.81,103.99 128.82,104.01 129.11,104.3 129.11,105.06 128.8,105.36 128.8,109.16 129.18,109.53 129.95,109.53
PHASE_CORE on BOTTOM (solid shape): 43.15,77 43.18,76.99 43.2,76.95 43.2,76.49 43.17,76.46 43.17,74.77 43.7,74.77 43.7,76.46 43.67,76.49 43.67,76.95 43.69,76.99 43.72,77 45.95,77 46.15,76.8 46.15,74.64 45.09,73.57 35.08,73.57 34.88,73.78 34.88,75.58 35.03,75.73 40.62,75.73 41.89,77
PHASE_CORE on BOTTOM (solid shape): 42.93,69.76 42.93,68.89 42.92,68.86 42.9,68.84 42.8,68.78 42.73,68.69 42.71,68.67 42.69,68.67 42.39,68.67 42.37,68.65 42.27,68.65 41.78,68.16 41.78,67.22 41.77,67.19 41.73,67.17 41.64,67.17 41.61,67.19 41.59,67.22 41.59,68.12 41.58,68.12 41.58,68.24 41.5,68.32 41.5,69 41.89,69.38 41.89,69.97 42.09,70.17 42.52,70.17
PHASE_VGG on TOP (solid shape): 127.99,62.47 127.99,61.36 127.74,61.1 126.16,61.1 125.25,62.02 125.25,63.03 125.45,63.24 127.23,63.24
PHASE_VGG on BOTTOM (solid shape): 125.73,64.35 125.73,63.72 125.99,63.46 130.56,63.46 130.68,63.34 130.68,61.31 130.18,60.8 122.68,60.8 122.43,61.05 122.43,62.28 122.58,62.43 124.21,62.43 124.21,62.97 122.59,62.97 122.43,63.13 122.43,64.48 122.81,64.86 125.22,64.86
PLLCPU_1P24_PWR on TOP (solid shape): 66.64,72.25 67.67,72.25 68.1,71.82 68.1,71.24 67.64,70.79 67.64,70.76 67.64,70.75 67.49,70.75 67.49,70.37 67.33,70.22 67.16,70.22 66.07,71.31 66.9,71.31 66.9,71.26 66.91,71.2 66.93,71.15 66.95,71.1 66.98,71.06 67.02,71.02 67.06,70.98 67.11,70.96 67.16,70.94 67.21,70.93 67.27,70.92 67.32,70.93 67.37,70.94 67.42,70.96 67.47,70.98 67.51,71.02 67.55,71.06 67.58,71.1 67.6,71.15 67.62,71.2 67.63,71.26 67.63,71.31 67.62,71.36 67.6,71.42 67.58,71.47 67.55,71.51 67.51,71.55 67.47,71.58 67.42,71.61 67.37,71.63 67.32,71.64 67.27,71.65 67.21,71.64 67.16,71.63 67.11,71.61 67.06,71.58 67.02,71.55 66.98,71.51 66.95,71.47 66.93,71.42 66.91,71.36 66.9,71.31 66.07,71.31 66.04,71.34 66.04,72.28 66.12,72.35 66.54,72.35
R_SPK+ on TOP (solid shape): 31.12,22.09 32.51,22.09 32.56,22.04 32.56,21.15 32.41,21 30.13,21 29.77,21.35 29.77,22.04 29.87,22.14 31.05,22.14 31.06,22.15
R_SPK+ on TOP (solid shape): 9.69,15.17 9.69,14.12 10.31,13.5 10.31,12.41 10.16,12.27 9.94,12.27 9.82,12.39 9.82,13.52 9.49,13.86 9.49,15.16 9.51,15.19 9.67,15.19
R_SPK+ on IN2 (solid shape): 31.45,22.01 31.45,21.58 31.13,21.26 30.6,21.26 29.91,20.58 29.3,21.19 30.28,22.16 31.29,22.16
R_SPK+ on IN2 (solid shape): 11.15,12.89 11.15,12.36 11.03,12.25 9.96,12.25 9.88,12.32 9.88,13.31 9.95,13.38 10.66,13.38
R_SPK+_1 on TOP (solid shape): 35.21,22.04 35.21,20.92 34.85,20.56 33.07,20.56 32.84,20.79 32.84,21.96 32.97,22.09 35.15,22.09
R_SPK+_1 on BOTTOM (solid shape): 36.6,24.8 36.6,22.29 34.79,20.48 33.85,20.48 33.71,20.62 33.71,21.17 33.99,21.45 34.57,21.45 35.18,22.06 35.18,25.13 35.33,25.28 36.12,25.28
R_SPK- on TOP (solid shape): 32.59,23.82 32.59,22.52 32.44,22.37 31.6,22.37 31.45,22.52 31.45,23.82 31.6,23.97 32.44,23.97
R_SPK- on TOP (solid shape): 9.29,15.18 9.29,14.17 9.38,14.08 9.38,13.78 9.65,13.51 9.65,12.4 9.52,12.27 9.27,12.27 9.12,12.42 9.12,13.49 9.09,13.52 9.09,15.17 9.1,15.19 9.28,15.19
R_SPK- on IN2 (solid shape): 32.61,22.77 32.61,21.63 31.73,21.63 31.73,22.11 31.41,22.43 31.41,22.81 31.54,22.94 32.45,22.94
R_SPK- on IN2 (solid shape): 9.6,13.28 9.6,12.18 9.86,11.92 10.89,11.92 10.9,11.9 10.9,11.01 9.55,11.01 9.22,11.34 9.22,13.29 9.28,13.36 9.53,13.36
R_SPK-_1 on TOP (solid shape): 35.22,23.7 35.22,22.49 35.1,22.37 32.94,22.37 32.84,22.47 32.84,23.71 32.94,23.82 35.1,23.82
R_SPK-_1 on BOTTOM (solid shape): 34.87,22.46 34.75,22.34 33.83,22.34 33.71,22.47 33.71,22.8 33.94,23.03 33.94,25.19 34.03,25.28 34.87,25.28
RING2 on TOP (solid shape): 10.59,21.91 10.59,21.75 10.43,21.58 9.42,21.58 9.29,21.44 9.29,20.47 9.24,20.42 9.13,20.42 9.09,20.46 9.09,21.57 9.58,22.06 10.44,22.06
RING2 on TOP (solid shape): 6.94,35.17 6.94,34.64 7.27,34.31 7.27,32.58 5.61,30.93 5.61,29.21 5.74,29.09 7.07,29.09 7.11,29.05 7.11,28.16 6.63,27.68 4.7,27.68 4.29,28.08 4.29,31.64 6.05,33.39 6.05,34.99 6.38,35.32 6.78,35.32
RING2 on IN2 (solid shape): 7.44,28.57 7.44,26.15 8.8,24.79 8.82,24.76 8.84,24.71 8.88,24.67 8.92,24.63 8.96,24.59 9.01,24.57 9.04,24.55 9.25,24.35 9.63,24.35 10.11,23.87 10.57,23.87 10.95,23.49 10.95,22.09 10.42,21.55 9.53,21.55 9.44,21.64 9.44,22.15 9.34,22.25 9.34,22.66 8.79,23.21 9.67,23.21 9.67,23.15 9.67,23.1 9.69,23.04 9.71,22.99 9.74,22.94 9.78,22.9 9.82,22.86 9.87,22.83 9.92,22.81 9.98,22.79 10.03,22.79 10.09,22.79 10.14,22.79 10.2,22.81 10.25,22.83 10.3,22.86 10.34,22.9 10.38,22.94 10.41,22.99 10.43,23.04 10.45,23.1 10.45,23.15 10.45,23.21 10.45,23.26 10.43,23.32 10.41,23.37 10.38,23.42 10.34,23.46 10.3,23.5 10.25,23.53 10.2,23.55 10.14,23.57 10.09,23.57 10.03,23.57 9.98,23.57 9.92,23.55 9.87,23.53 9.82,23.5 9.78,23.46 9.74,23.42 9.71,23.37 9.69,23.32 9.67,23.26 9.67,23.21 8.79,23.21 8.5,23.5 8.5,23.52 6.41,25.62 5.93,26.09 5.93,28.71 6.15,28.92 7.09,28.92
RING2_R on TOP (solid shape): 6.02,38.65 6.02,38.63 6.77,37.87 6.77,37.83 6.87,37.74 7.86,37.74 8.19,37.41 8.19,34.87 8.1,34.79 7.16,34.79 7.16,34.79 7.16,35.46 7.53,35.86 7.16,36.25 7.16,36.41 7.15,36.42 7.15,36.83 6.98,37 5.06,37 3.6,38.46 3.3,38.46 3.29,38.46 2.79,38.46 2.77,38.48 2.77,38.95 2.96,39.14 5.53,39.14
RING2_R on BOTTOM (solid shape): 6.02,38.65 6.02,38.21 6.85,37.38 6.85,36.33 6.77,36.25 5.3,36.25 4.49,37.06 4.49,37.56 3.58,38.47 3.12,38.47 3.12,38.46 2.78,38.46 2.77,38.47 2.77,38.95 2.96,39.14 5.53,39.14
SLEEVE on TOP (solid shape): outline of 96 points within 7.81,30.12 17.06,48.71
SLEEVE on IN2 (solid shape): 9.19,31.38 9.19,30.54 7.85,29.19 6.09,29.19 5.73,28.84 5.73,26 8.1,23.63 8.1,23.63 8.28,23.45 8.28,23.43 8.9,22.82 9.13,22.58 9.13,21.76 8.77,21.41 8.61,21.41 6.92,23.09 6.92,23.16 6.85,23.4 6.63,23.55 4.64,25.54 4.64,29.72 5.42,30.49 7.22,30.49 7.23,30.5 7.43,30.5 7.97,31.04 7.97,31.47 8.27,31.78 8.8,31.78
SLEEVE_R on TOP (solid shape): 14.89,50.46 15.53,50.46 16.07,49.93 16.09,49.92 16.28,49.75 16.51,49.69 17.06,49.69 17.11,49.64 17.42,49.5 17.78,49.61 17.81,49.59 17.91,49.49 17.91,49.11 17.78,48.99 15.4,48.99 15.21,49.17 14.85,49.32 14.42,49.13 14.35,49.16 14,49.51 13.93,49.58 12.49,49.58 11.95,49.04 5.22,49.04 4.2,48.02 3.11,48.02 3.04,48.09 3.04,48.67 4.62,50.25 5.71,50.25 6.2,50.74 14.61,50.74
TOUCH_SCREEN_PWR on TOP (solid shape): 69.44,101.51 69.44,100.55 68.83,99.94 68.81,99.92 68.78,99.93 68.31,99.82 68.35,99.35 68.4,99.3 68.4,97.6 68.36,97.52 68.26,97.51 67.89,97.45 67.77,97.1 67.75,97.01 67.67,96.97 66.69,96.97 66.57,97.09 66.57,101.56 66.7,101.69 69.27,101.69
TOUCH_SCREEN_PWR on BOTTOM (solid shape): 67.74,97.42 67.74,96.94 67.64,96.84 66.96,96.84 66.63,96.51 66.52,96.51 66.51,96.5 66.41,96.4 66.38,96.4 66.38,96.36 66.37,96.36 66.37,95.09 66.32,95.04 66.19,95.04 66.16,95.07 66.15,95.07 66.12,95.1 66.12,96.4 65.88,96.4 65.88,95.12 65.86,95.08 65.83,95.07 65.76,95.07 65.62,95.2 65.62,96.4 65.61,96.4 65.61,96.76 65.69,96.85 66.12,96.85 66.21,96.94 66.22,96.94 66.36,97.04 66.43,97.2 66.44,97.21 66.8,97.58 67.59,97.58
TPM_VDD on BOTTOM (solid shape): 128.29,75.34 129.85,75.34 129.96,75.23 130.28,75.23 130.31,75.21 131.69,75.21 131.76,75.13 131.76,74.73 131.62,74.58 129.84,74.58 129.73,74.47 129.72,74.47 129.38,74.13 128.03,74.13 127.8,74.36 127.8,74.37 127.54,74.51 127.26,74.42 127,74.42 126.96,74.43 126.91,74.44 126.79,74.56 126.79,75.36 126.92,75.49 128.14,75.49
TPM_VDD on BOTTOM (solid shape): 140.6,74.35 140.6,73.85 141.1,73.34 141.11,73.33 141.12,73.31 141.12,72.8 141.11,72.78 141.03,72.68 141,72.59 141,72.29 141.03,72.19 141.11,72.09 141.12,72.07 141.12,71.84 141.1,71.82 141.09,71.81 141.02,71.73 140.99,71.63 140.99,71.35 141.05,71.21 141.2,71.14 141.27,71.14 141.29,71.14 141.31,71.13 141.38,71.06 141.68,71.06 141.78,70.96 141.78,70.55 141.63,70.4 138.89,70.4 138.55,70.74 138.55,70.78 138.06,71.27 138.02,71.27 137.92,71.36 136.53,71.36 136.44,71.28 136.41,71.28 136.41,71.25 135.98,70.82 135.79,70.82 135.49,71.12 134.63,71.12 134.59,71.13 134.58,71.17 134.58,71.82 135.54,72.78 135.58,72.8 135.62,72.78 136.41,71.99 136.41,71.96 136.44,71.96 136.45,71.95 138.4,71.95 138.58,71.91 138.74,71.94 138.75,71.95 138.91,71.95 139.12,71.75 139.12,71.72 139.1,71.66 139.1,71.62 139.1,71.32 139.16,71.17 139.31,71.11 139.59,71.11 139.73,71.17 139.8,71.32 139.8,71.62 139.79,71.68 139.76,71.73 139.76,71.76 139.77,71.79 139.9,71.92 139.9,73.8 139.88,73.83 139.88,74.34 140.01,74.46 140.49,74.46
UGATE_VCORE on BOTTOM (solid shape): 40.39,72.23 40.39,71.34 40.21,71.16 39.5,71.16 39.37,71.03 38.66,71.03 38.61,71.08 38.61,71.75 38.66,71.8 39.19,71.8 39.5,72.1 39.5,72.28 39.7,72.48 40.13,72.48
UGATE_VGG on TOP (solid shape): 121.08,54.8 121.08,54.35 121.24,54.19 121.24,54.04 121.22,54.01 121.18,53.99 120.42,53.99 120.3,54.12 120.3,54.63 119.94,54.98 119.94,55.26 120.04,55.36 120.52,55.36
UGATE_VGG on BOTTOM (solid shape): 126.83,66.18 126.83,65.37 126.67,65.22 125.55,65.22 125.25,65.52 125.25,66.03 125.5,66.28 126.72,66.28
USB_3P3_PWR on BOTTOM (solid shape): 76.96,87.32 76.79,87.14 75.92,87.14 75.7,86.92 75.7,86.88 75.63,86.81 75.63,85.87 75.64,85.77 75.68,85.67 75.68,85.33 74.96,84.61 74.96,83.36 74.7,83.1 74.43,82.96 74.32,82.64 74.29,82.62 74.2,82.6 74.12,82.54 73.57,82.54 73.57,82.72 73.58,82.74 73.66,83.03 73.51,83.29 73.51,84.17 74.86,85.51 74.86,86.93 75.16,87.24 75.16,87.82 75.64,88.31 76.96,88.31
V_BLIGHT on BOTTOM (solid shape): outline of 191 points within 54.97,92.8 63.73,98.41
VA1 on BOTTOM (solid shape): 13.78,102.05 16.7,100.51 19.88,101.36 24.33,101.36 25.17,100.52 25.17,94.68 24.92,94.43 22.56,94.43 22.54,94.44 22.26,94.44 21.06,95.65 20.09,95.65 19.89,95.44 19.89,94.33 19.51,93.94 18.03,93.94 18,93.96 18,93.98 17.65,94.23 17.31,93.98 17.3,93.96 17.28,93.94 14.61,93.94 13.62,94.94 13.62,98.67 12.88,99.41 6.84,99.41 6.42,99.83 6.42,100.45 5.97,100.9 5.97,102.05 6.1,102.17 13.65,102.17
VA1 on IN1 (solid shape): 13.39,102.57 15.4,100.85 18.02,100.55 18.76,99.81 18.76,96.07 16.96,94.26 14.29,94.26 13.73,94.82 13.73,96.84 13.96,99.49 11.7,100.88 11.67,100.88 11.59,100.8 11.59,99.85 11.23,99.49 7.09,99.49 6.75,99.82 6.75,102.07 7.26,102.57
VA1 on IN2 (solid shape): 13.37,102.6 14.52,101.36 16.04,100.63 16.05,100.63 16.64,100.04 16.64,97.29 14.69,95.34 14.1,95.34 13.82,95.62 13.82,96.96 13.92,97.13 14.01,97.31 14.25,97.55 14.25,99.46 12.78,100.93 11.71,100.93 11.6,100.82 11.6,99.9 11.2,99.5 6.96,99.5 6.4,100.06 6.4,101.82 7.18,102.6
VA2 on BOTTOM (solid shape): 17.32,93.7 17.33,93.69 17.65,93.48 17.98,93.69 18,93.71 18.03,93.72 20.78,93.72 21.72,92.78 23.39,92.78 23.72,92.45 23.72,88.66 23.66,88.59 23.62,88.56 23.59,88.53 23.32,88.26 16.23,88.26 15.71,88.78 15.7,88.8 15.71,88.82 15.72,88.89 15.71,88.97 15.7,89.02 15.67,89.08 15.67,90.19 15.34,90.52 15.34,93.16 15.9,93.72 17.3,93.72
N18218785 on BOTTOM (solid shape): 65.2,93.89 65.2,92.29 65.63,91.86 65.63,90.64 65.53,90.54 51.6,90.54 50.59,91.56 50.58,91.58 50.5,91.79 50.3,91.9 50.29,91.91 50.04,92.15 49.99,92.15 49.74,92.4 48.06,92.4 47.98,92.48 47.98,93.05 47.99,93.07 48,93.08 48.12,93.2 51.66,93.2 53.38,91.48 62.1,91.48 62.84,92.22 63.5,92.22 63.93,92.65 63.93,93.87 64.09,94.02 65.08,94.02
N21085249 on BOTTOM (solid shape): 29.13,92.55 29.13,87.9 29.13,87.89 29.1,87.77 29.12,87.64 29.12,87.61 29.11,87.59 28.45,86.93 25.3,86.93 25.2,87.04 25.2,87.37 24.77,87.8 24.31,87.8 24.17,87.93 24.17,88.1 24.22,88.41 24.01,88.64 23.99,88.66 23.98,88.69 23.98,92.17 24.66,92.85 28.83,92.85
N21086370 on BOTTOM (solid shape): 83.49,28.69 83.49,25.77 83.62,25.64 83.62,21.53 83.52,21.43 81.79,21.43 80.98,22.24 80.98,29.2 81.05,29.28 82.91,29.28
N21086566 on TOP (solid shape): 93.37,23.74 93.42,23.74 93.76,23.4 94.37,23.4 94.45,23.33 94.45,22.85 94.37,22.77 92.29,22.77 92.15,22.92 92.15,23.49 91.98,23.66 91.98,23.68 91.96,23.68 91.21,24.43 90.91,24.43 90.83,24.5 90.83,25.01 90.91,25.09 92.03,25.09
N21092228 on BOTTOM (solid shape): 111.17,101.04 112.16,101.04 112.17,101.03 112.17,100.89 112.15,100.86 112.12,100.84 111.17,100.84 111.17,100.64 112.12,100.64 112.15,100.63 112.17,100.59 112.17,100.29 111.56,99.69 111.56,98.31 110.85,97.6 110.85,95.44 110.54,95.14 108.28,95.14 107.93,95.49 107.93,99.51 108.71,100.29 109.88,100.29 110.28,100.69 110.39,100.69 110.61,100.92 110.64,100.96 110.67,101.01 110.71,101.06 111.17,101.06
N21092230 on BOTTOM (solid shape): 104.62,98.8 104.62,94.49 105.44,93.67 105.44,92.57 105.35,92.47 100.23,92.47 99.8,92.9 99.8,96.99 99.7,97.09 99.15,97.09 99,97.24 99,98.1 99.09,98.19 101.42,98.19 101.44,98.2 101.56,98.2 102.69,99.33 104.09,99.33
N21092239 on BOTTOM (solid shape): 116.61,100.88 117.04,100.88 117.17,100.75 117.17,100.5 117,100.33 116.8,100.33 116.63,100.49 116.63,100.58 116.36,100.85 115.39,100.85 115.39,101.03 116.46,101.03
N21092313 on BOTTOM (solid shape): outline of 85 points within 99.6,100.8 104.01,111.75
N21092424 on BOTTOM (solid shape): outline of 99 points within 111,92.37 119.03,100.27
N21094874 on BOTTOM (solid shape): 32.77,44.62 32.77,39.46 33.06,39.17 34.18,39.17 36.23,37.11 36.23,33.05 36.04,32.86 34.85,32.86 34.61,33.1 34.61,33.61 34.63,33.62 34.63,34.62 34.53,34.71 28.59,34.71 27.96,34.08 22.43,34.08 21.79,34.71 21.79,38.71 22.5,39.42 26.82,39.42 28.98,41.58 28.98,44.47 29.47,44.95 32.44,44.95
N21094973 on TOP (solid shape): 26.21,46.19 26.21,44.16 26.01,43.96 24.94,43.96 24.54,44.36 24.54,45.99 24.87,46.32 26.09,46.32
N21102772 on TOP (solid shape): 86.16,104.89 86.26,104.83 86.24,104.72 86.35,104.16 86.87,104.42 86.94,104.49 87.04,104.47 87.12,104.38 87.12,102.05 86.31,101.23 85.14,101.23 84.94,101.44 84.94,104.51 85.32,104.89
N21132627 on TOP (solid shape): 11.61,13.68 11.61,12.36 11.74,12.23 11.74,11.65 11.61,11.52 8.05,11.52 7.34,12.23 7.34,13.27 7.39,13.33 7.62,13.33 7.67,13.27 7.67,12.44 7.73,12.38 7.73,12.36 7.93,12.16 7.95,12.16 8.09,12.15 8.18,12.16 8.66,12.16 8.75,12.15 8.84,12.16 9.32,12.16 9.41,12.15 9.5,12.16 9.98,12.16 10.07,12.15 10.24,12.16 10.44,12.36 10.44,13.81 10.49,13.86 11.43,13.86
N21604905 on BOTTOM (solid shape): outline of 129 points within 134.77,105.27 147.72,109.79
N24510304 on TOP (solid shape): 152.03,54.5 152.03,52.88 151.9,52.75 150.25,52.75 149.76,53.12 149.11,53.23 149.07,53.26 148.9,53.43 148.9,53.56 148.5,53.97 148.5,54.3 148.79,54.59 151.94,54.59
N24510304 on BOTTOM (solid shape): 152.32,71.38 152.32,70.86 152.31,70.85 150.77,70.85 150.76,70.84 150.76,70.66 150.77,70.65 152.32,70.65 152.32,70.65 152.32,70.35 152.32,70.35 150.7,70.35 150.5,70.15 150.5,69.71 150.32,69.53 149.23,69.53 148.97,69.8 148.97,70.83 149.17,71.03 149.88,71.24 150.24,71.89 151.81,71.89
N24510304 on BOTTOM (solid shape): 150.41,56.09 150.41,54.33 150.6,54.14 152.31,54.14 152.32,54.13 152.32,53.85 152.31,53.85 150.77,53.85 150.76,53.84 150.76,53.65 150.77,53.65 152.32,53.65 152.32,53.65 152.32,53.36 152.31,53.35 150.77,53.35 150.76,53.34 150.76,53.16 150.77,53.15 152.31,53.15 152.32,53.14 152.32,52.87 152.3,52.85 150.16,52.85 150,52.99 149.81,53.1 149.43,53.22 149.03,53.2 148.94,53.22 148.9,53.3 148.78,53.58 148.4,53.69 148.37,53.76 148.37,53.83 148.36,53.84 148.36,54.37 149.05,55.06 149.05,56.28 150.22,56.28
N26412554 on TOP (solid shape): 133.94,99.15 133.94,96.97 133.81,96.84 132.18,96.84 131.82,97.21 131.81,97.21 131.59,97.43 131.59,99.12 131.78,99.3 133.78,99.3
N26412554 on BOTTOM (solid shape): 134.27,100.58 134.27,97.53 133.94,97.2 133.94,95.8 133.81,95.67 133.38,95.67 133.2,95.85 133.2,96.46 132.82,96.84 130.48,96.84 130.28,97.04 130.28,100.65 130.41,100.78 134.06,100.78
N26423000 on BOTTOM (solid shape): 124.03,112.56 124.03,111.22 124.31,110.94 126.95,110.94 127.08,110.81 127.08,109.52 127.99,108.6 127.99,105.91 127.18,105.1 127.18,104.28 128.53,102.94 128.53,102.15 127.92,101.54 125.73,101.54 125.31,101.12 121.42,101.12 121.3,101.23 121.3,101.8 121.51,102.01 121.51,107.66 122.1,108.25 122.1,112.77 122.48,113.15 123.45,113.15
N241918800 on TOP (solid shape): 130.38,62.68 130.38,61.69 130.23,61.53 129.19,61.53 129.03,61.38 128.22,61.38 128.14,61.46 128.14,62.55 128.47,62.88 130.18,62.88

Small or netless copper shapes (teardrops, artwork), in the pictures only: 50 on TOP, 16 on BOTTOM, 15 on IN1, 6 on IN2

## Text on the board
BOTTOM: USB | LPC CLK | LPC
Ref Des/Silkscreen Bottom: DA0ZHXMB6C0 REV:C
User.Comments: PARTITION_2
Ref Des/Silkscreen Top: MODEL:ZHX | DA0ZHXMB6C0 REV:C
VCC: VCC | 2
IN2: HDMI | USB | eDP | AUDIO | eMMC | SATA | PCIE
GND: GND | 5
User.12: +VCC_CORE | +VIN | +1.8V_S5 | ADOGND | +5v | GND | +3v | +1.05V_S5 | +VGG | +5V_s5 | +5V_HDD
User.29: REV:A-8
User.30: ADOGND | GND
User.45: Excess check:Nov 10 12:24:20 2015 | PadStack_Check:Nov 10 12:12:33 2015 | TP check:Nov 10 12:13:01 2015 | XY-Check acute:Nov 10 12:36:18 2015 | XY-Check rotation:Nov 10 13:03:37 2015 | XY-Create plane:Dec 22 10:18:37 2015 | XY-Dxf to pin check:Nov 10 12:21:09 2015 | XY-Etch cross-GND-BOTTOM:Nov 10 12:37:03 2015 | XY-Etch cross-IN1-IN2:Nov 10 12:37:00 2015 | XY-Etch cross-TOP-VCC:Nov 10 12:36:57 2015 | XY-Excess check:Nov 10 12:24:20 2015 | XY-Mask check:Nov 10 12:49:41 2015 | XY-Outline check:Dec 21 15:21:40 2015 | XY-PadStack_Check:Nov 10 12:12:33 2015 | XY-Plane net check:Nov 10 12:23:26 2015 | XY-Prop check:Nov 10 12:36:54 2015 | XY-Symbol cross:Nov 10 12:24:45 2015 | XY-TP check:Nov 10 12:13:01 2015 | XY-shape min check:Nov 10 12:11:57 2015 | XY-shape pin check:Nov 10 12:49:50 2015 | XY-via check:Nov 10 12:37:34 2015 | check acute:Nov 10 12:36:18 2015 | check rotation:Nov 10 13:03:37 2015 | create nettxt:Nov 08 14:25:33 2015 | create plane:Dec 22 10:18:37 2015 | dxf to pin check:Nov 10 12:21:09 2015 | etch cross-GND-BOTTOM:Nov 10 12:37:03 2015 | etch cross-IN1-IN2:Nov 10 12:37:00 2015 | etch cross-TOP-VCC:Nov 10 12:36:57 2015 | outline check:Dec 21 15:21:40 2015 | plane net check:Nov 10 12:23:26 2015 | prop check:Nov 10 12:36:54 2015 | shape min check:Nov 10 12:11:57 2015 | shape pin check:Nov 10 12:49:50 2015 | symbol cross:Nov 10 12:24:45 2015 | via check:Nov 10 12:37:34 2015 | FIGURE | TYPE | Circle | Oblong | SIZE | 10.0 | 12.0 | 14.0 | 20.0 | 22.0 | 28.0 | 32.0 | 110.0 | 134.0 | 157.0 | 31.0 | 41.0 | 43.0 | 47.0 | 63.0 | 67.0 | 118.0 | 46.0x24.0 | 59.0x24.0 | 69.0x20.0 | 71.0x31.0 | 79.0x28.0 | 82.0x39.0 | 87.0x43.0 | 100.0x31.0 | 102.0x31.0 | 142.0x134.0 | 37.0x33.0 | 142.0x118.0 | 158.0x118.0 | DRILL CHART: TOP to BOTTOM | ALL UNITS ARE IN MILS | PLATED | NON-PLATED | ROTATION | - | 0.000 | QTY | 3159 | 4 | 287 | 33 | 19 | 22 | 9 | 2 | 1 | 3553 | 7 | 3 | 29 | TOTAL HOLES:
